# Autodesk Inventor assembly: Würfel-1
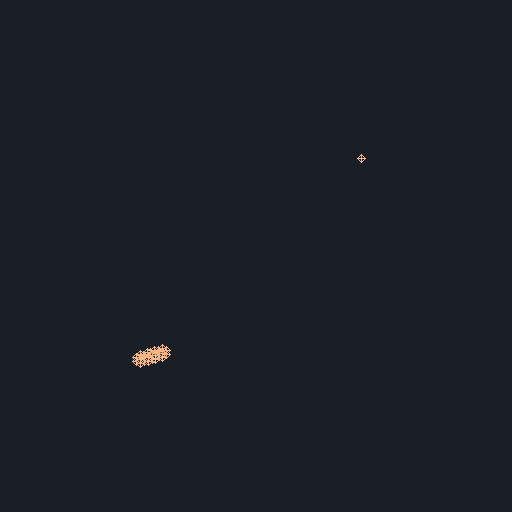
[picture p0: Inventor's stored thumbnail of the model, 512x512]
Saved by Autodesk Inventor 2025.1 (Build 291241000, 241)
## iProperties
Company: Ed. Züblin AG
Created: 2021-07
Part Number: Würfel-1
Material: Stahlbeton C30/37
Document SubType Name: Assembly
Designer: Eimannsmir
Mass: 14.8261 g
Surface Area: 31.3494 cm^2
Volume: 5.93044 cm^3
Density: 2.5 g/cm^3
z_Bereich: Tunnelbau
z_Direktion: Tief- und Tunnelbau
z_Konzerneinheit: Zentrale Technik
cpiComponentType: Attribut
cpiFitMatchkey: =<z_Matchkey>
z_Matchkey: =<z_Matchkey_010>_<z_Matchkey_020>_<z_Matchkey_030>_<z_Matchkey_040>_<z_Matchkey_050>_<z_Matchkey_060>_<z_Matchkey_070>_<z_Matchkey_080>_<z_Matchkey_090>_<z_Mat
z_Matchkey_010: xxxxx
z_Matchkey_020: 5DTUB
z_Matchkey_030: xxx
z_Matchkey_040: xxx
z_Matchkey_050: xxx
z_Matchkey_060: xxx
z_Matchkey_070: xxx
z_Matchkey_080: xxx
z_Matchkey_090: xxx
z_Matchkey_100: xxx
z_Matchkey_110: xxx
z_Matchkey_120: xxxxxxx
z_Matchkey_130: xxxx
z_Matchkey_140: xxxx
DocNumber: Würfel-1.iam
Folder: Übung\
VDS_Category: Konstruktion
Koordinate x - Ursprung: 0.0
Koordinate y - Ursprung: 0.0
Koordinate z - Ursprung: 0.0
Rotation - z-Achse: 0.0
Author: Eimannsmir
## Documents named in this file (2)
- C:\z_Vault\CAD\Übung\Würfel-1.iam
- C:\z_Vault\CAD\Übung\Würfel-1.ipt
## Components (4 placed, 1 different names)
1. Würfel-1:1
2. Würfel-1:2
3. Würfel-1:3
4. Würfel-1:4
